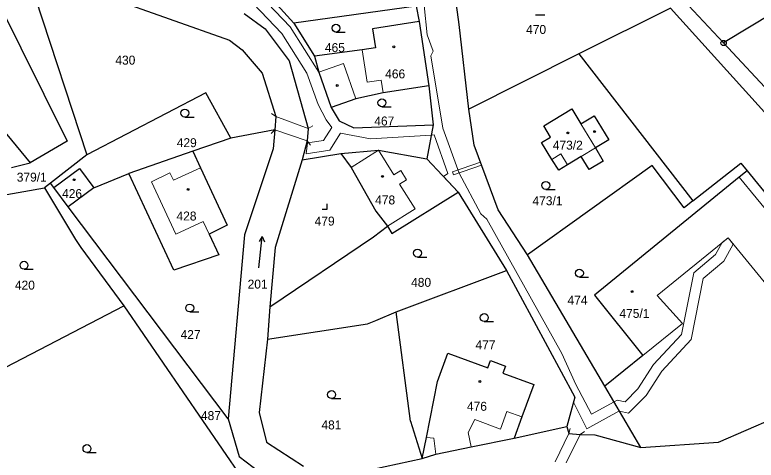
# Model space of a CAD drawing. Extents: x -727701 to -724405, y -960481 to -957284.
# Drawn here: x -726812.2 to -726671.5, y -958402.3 to -958317.7 of the extents above; entities that cross this region are included whole.
import ezdxf
from ezdxf.enums import TextEntityAlignment as Align

# ---------------------------------------------------------------- set-up
doc = ezdxf.new("R2010")
doc.units = 0
doc.header["$LTSCALE"] = 0.68
for name, color, linetype, lineweight in [('1', 7, 'Continuous', 25), ('13', 7, 'Continuous', 13), ('3', 7, 'Continuous', 25), ('4', 7, 'Continuous', 13), ('5', 7, 'Continuous', 25), ('8', 7, 'Continuous', 25)]:
    doc.layers.add(name, color=color, linetype=linetype, lineweight=lineweight)
doc.layers.add('2', color=7, linetype='Continuous')

msp = doc.modelspace()

# ---------------------------------------------------------------- linework, layer by layer
at = {"layer": '1'}
for p, q in [((-726618.94, -958287.19), (-726677.69, -958323.03)), ((-726772.79, -958304.36), (-726759.23, -958319.25)), ((-726810.21, -958308.73), (-726771.46, -958322.52)), ((-726810.21, -958308.73), (-726798.51, -958344.29)), ((-726727.9, -958319.49), (-726729.36, -958308.42)), ((-726818.24, -958309.55), (-726802.3, -958341.7)), ((-726736.03, -958316.02), (-726759.23, -958319.25)), ((-726736.03, -958316.02), (-726735.5, -958318.98)), ((-726687.74, -958316.39), (-726705.14, -958325.12)), ((-726687.74, -958316.39), (-726665.6, -958341)), ((-726684.33, -958315.89), (-726677.69, -958323.03)), ((-726768.67, -958317.43), (-726764.7, -958320.37)), ((-726759.23, -958319.25), (-726755.31, -958325.53)), ((-726735.5, -958318.98), (-726744.32, -958320.32)), ((-726735.5, -958318.98), (-726733.65, -958331.2)), ((-726764.7, -958320.37), (-726760.13, -958326.43)), ((-726744.32, -958320.32), (-726743.76, -958323.97)), ((-726726.02, -958335.6), (-726727.9, -958319.49)), ((-726771.46, -958322.52), (-726769.08, -958324.31)), ((-726677.69, -958323.03), (-726664, -958337.75)), ((-726769.08, -958324.31), (-726765.28, -958328.77)), ((-726746.29, -958324.36), (-726755.31, -958325.53)), ((-726743.76, -958323.97), (-726746.29, -958324.36)), ((-726755.31, -958325.53), (-726754.54, -958328.58)), ((-726705.14, -958325.12), (-726726.02, -958335.6)), ((-726705.14, -958325.12), (-726683.51, -958353.02)), ((-726760.13, -958326.43), (-726756.52, -958339.29)), ((-726765.28, -958328.77), (-726762.66, -958336.97)), ((-726754.54, -958328.58), (-726752.19, -958335.27)), ((-726733.65, -958331.2), (-726742.33, -958332.52)), ((-726733.65, -958331.2), (-726732.83, -958338.56)), ((-726819.9, -958332.9), (-726809.31, -958345.8)), ((-726775.94, -958332.49), (-726798.51, -958344.29)), ((-726771.24, -958341.08), (-726775.94, -958332.49)), ((-726742.33, -958332.52), (-726747.47, -958333.61)), ((-726747.47, -958333.61), (-726752.19, -958335.27)), ((-726752.19, -958335.27), (-726750.65, -958337.84)), ((-726725.06, -958342.42), (-726726.02, -958335.6)), ((-726711.82, -958338.77), (-726706.51, -958335.56)), ((-726706.51, -958335.56), (-726704.78, -958338.4)), ((-726762.66, -958336.97), (-726762.86, -958339.53)), ((-726750.65, -958337.84), (-726747.86, -958339.12)), ((-726747.86, -958339.12), (-726732.83, -958338.56)), ((-726732.83, -958338.56), (-726734, -958345.05)), ((-726710.53, -958340.89), (-726711.82, -958338.77)), ((-726762.86, -958339.53), (-726771.24, -958341.08)), ((-726762.86, -958339.53), (-726763.16, -958343.11)), ((-726756.52, -958339.29), (-726756.71, -958341.61)), ((-726802.3, -958341.7), (-726809.31, -958345.8)), ((-726771.24, -958341.08), (-726778.41, -958343.59)), ((-726756.71, -958341.61), (-726757.7, -958345.2)), ((-726712.26, -958341.96), (-726710.53, -958340.89)), ((-726699.47, -958341.43), (-726702, -958342.97)), ((-726763.16, -958343.11), (-726768.64, -958359.47)), ((-726720.45, -958354.72), (-726725.06, -958342.42)), ((-726710.32, -958345.14), (-726712.26, -958341.96)), ((-726702, -958342.97), (-726700.56, -958345.49)), ((-726798.51, -958344.29), (-726805.45, -958349.64)), ((-726778.41, -958343.59), (-726790.55, -958347.84)), ((-726778.41, -958343.59), (-726776.96, -958346.73)), ((-726757.7, -958345.2), (-726750.35, -958344)), ((-726750.35, -958344), (-726743.18, -958343.39)), ((-726750.35, -958344), (-726748.4, -958346.65)), ((-726743.18, -958343.39), (-726734, -958345.05)), ((-726704.71, -958344.62), (-726707.3, -958346.19)), ((-726703.2, -958347.09), (-726704.71, -958344.62)), ((-726812.83, -958346.68), (-726809.31, -958345.8)), ((-726757.7, -958345.2), (-726762.82, -958361.87)), ((-726734, -958345.05), (-726728.06, -958351.35)), ((-726708.97, -958347.17), (-726710.32, -958345.14)), ((-726700.56, -958345.49), (-726703.2, -958347.09)), ((-726683.51, -958353.02), (-726674.43, -958345.88)), ((-726674.43, -958345.88), (-726673.24, -958347.31)), ((-726804.82, -958350.47), (-726799.9, -958346.86)), ((-726799.9, -958346.86), (-726797.21, -958350.55)), ((-726776.96, -958346.73), (-726771.91, -958357.66)), ((-726748.4, -958346.65), (-726743.69, -958354.99)), ((-726707.3, -958346.19), (-726708.97, -958347.17)), ((-726673.24, -958347.31), (-726674.73, -958348.52)), ((-726673.24, -958347.31), (-726646.16, -958380.52)), ((-726797.21, -958350.55), (-726790.55, -958347.84)), ((-726782.03, -958366.2), (-726790.55, -958347.84)), ((-726674.73, -958348.52), (-726702.18, -958370.9)), ((-726805.45, -958349.64), (-726806.58, -958350.51)), ((-726804.82, -958350.47), (-726805.45, -958349.64)), ((-726830.51, -958354.75), (-726806.58, -958350.51)), ((-726806.58, -958350.51), (-726800.69, -958360.38)), ((-726802.1, -958354.14), (-726804.82, -958350.47)), ((-726797.21, -958350.55), (-726802.1, -958354.14)), ((-726740.66, -958359.19), (-726728.06, -958351.35)), ((-726728.06, -958351.35), (-726718.91, -958366.22)), ((-726771.73, -958394.42), (-726802.1, -958354.14)), ((-726743.69, -958354.99), (-726741.45, -958357.8)), ((-726771.91, -958357.66), (-726775.33, -958359.34)), ((-726744.13, -958359.87), (-726741.45, -958357.8)), ((-726741.45, -958357.8), (-726740.66, -958359.19)), ((-726775.33, -958359.34), (-726773.5, -958363.29)), ((-726768.64, -958359.47), (-726771.73, -958394.42)), ((-726763.84, -958373.14), (-726744.13, -958359.87)), ((-726800.69, -958360.38), (-726799.66, -958361.88)), ((-726799.66, -958361.88), (-726791.52, -958372.96)), ((-726762.82, -958361.87), (-726763.84, -958373.14)), ((-726773.5, -958363.29), (-726782.03, -958366.2)), ((-726700.25, -958388.21), (-726714.91, -958363.29)), ((-726739.83, -958374.1), (-726718.91, -958366.22)), ((-726718.91, -958366.22), (-726705.95, -958390.31)), ((-726702.18, -958370.9), (-726693.03, -958382.39)), ((-726835.12, -958395.65), (-726791.52, -958372.96)), ((-726791.52, -958372.96), (-726766.75, -958409.03)), ((-726763.84, -958373.14), (-726764.28, -958379.3)), ((-726743.71, -958375.73), (-726739.83, -958374.1)), ((-726737.11, -958394.87), (-726739.83, -958374.1)), ((-726764.28, -958379.3), (-726745.29, -958376.39)), ((-726745.29, -958376.39), (-726743.71, -958375.73)), ((-726764.28, -958379.3), (-726765.86, -958393.21)), ((-726731.96, -958387.31), (-726730.01, -958381.95)), ((-726730.01, -958381.95), (-726722.42, -958384.71)), ((-726693.03, -958382.39), (-726700.25, -958388.21)), ((-726722.42, -958384.71), (-726721.93, -958383.34)), ((-726721.93, -958383.34), (-726719.06, -958384.39)), ((-726719.06, -958384.39), (-726719.56, -958385.75)), ((-726719.56, -958385.75), (-726713.71, -958387.87)), ((-726734.1, -958397.95), (-726731.96, -958387.31)), ((-726713.71, -958387.87), (-726715.96, -958394.06)), ((-726693.41, -958399.84), (-726700.25, -958388.21)), ((-726705.95, -958390.31), (-726707.46, -958395.89)), ((-726678.65, -958398.83), (-726661.65, -958391.45)), ((-726765.86, -958393.21), (-726764.41, -958398.83)), ((-726771.73, -958394.42), (-726769.65, -958401.57)), ((-726737.11, -958394.87), (-726734.9, -958401.93)), ((-726715.96, -958394.06), (-726717.42, -958398.08)), ((-726717.42, -958398.08), (-726707.46, -958395.89)), ((-726707.46, -958395.89), (-726707.07, -958397.19)), ((-726734.9, -958401.93), (-726734.1, -958397.95)), ((-726725.6, -958399.75), (-726717.42, -958398.08)), ((-726707.07, -958397.19), (-726704.94, -958397.37)), ((-726704.94, -958397.37), (-726702.12, -958397.48)), ((-726702.12, -958397.48), (-726693.41, -958399.84)), ((-726764.41, -958398.83), (-726757.41, -958403.41)), ((-726693.41, -958399.84), (-726678.65, -958398.83)), ((-726732.3, -958401.15), (-726725.6, -958399.75)), ((-726769.65, -958401.57), (-726760.44, -958408.49)), ((-726746.61, -958404.51), (-726734.9, -958401.93)), ((-726734.9, -958401.93), (-726732.3, -958401.15))]:
    msp.add_line(p, q, dxfattribs=at)
for points in [[(-726704.78, -958338.4), (-726702.25, -958336.87), (-726699.47, -958341.43)], [(-726691.27, -958346.27), (-726714.91, -958363.29), (-726720.45, -958354.72)], [(-726683.51, -958353.02), (-726685.16, -958354.32), (-726691.27, -958346.27)]]:
    msp.add_lwpolyline(points, dxfattribs=at)
at = {"layer": '13'}
for points in [[(-726779.07, -958302.81), (-726761.52, -958321.23), (-726756.76, -958328.78), (-726754.62, -958334.72), (-726753.09, -958337.62), (-726752.07, -958339.07), (-726753.63, -958341.55), (-726756.66, -958342), (-726756.94, -958344.07), (-726752.42, -958343.4), (-726750.39, -958340.15), (-726744.7, -958341.22), (-726733.19, -958340.53), (-726732.63, -958340.5), (-726730.02, -958347.79), (-726730.85, -958348.39), (-726728.06, -958351.35), (-726718.91, -958366.22), (-726705.95, -958390.31), (-726706.21, -958391.28), (-726703.63, -958396.29), (-726697.55, -958392.97), (-726697.44, -958392.99), (-726695.72, -958393.33), (-726692.4, -958390), (-726689.43, -958385.35), (-726683.82, -958379.33), (-726681.54, -958367.75), (-726677.64, -958364.49), (-726675.86, -958361.23), (-726676.84, -958360.02), (-726677.99, -958360.95), (-726679.21, -958363.19), (-726683.37, -958366.67), (-726685.68, -958378.39), (-726691.02, -958384.12), (-726693.97, -958388.74), (-726696.38, -958391.16), (-726697.87, -958390.86), (-726698.49, -958391.2), (-726702.79, -958393.55), (-726705.72, -958387.88), (-726708.39, -958381.98), (-726722.61, -958356.49), (-726723.79, -958355.48), (-726727.9, -958347.77), (-726730.97, -958339.2), (-726733.23, -958325.48), (-726732.83, -958324.58), (-726733.92, -958321.51), (-726734.49, -958315.91)], [(-726732.83, -958338.56), (-726747.86, -958339.12), (-726750.65, -958337.84), (-726752.19, -958335.27), (-726754.54, -958328.58), (-726759.93, -958319.99), (-726774.12, -958305.1)], [(-726736.03, -958316.02), (-726735.5, -958318.98), (-726733.65, -958331.2), (-726732.83, -958338.56)]]:
    msp.add_lwpolyline(points, dxfattribs=at)
msp.add_lwpolyline([(-726729.16, -958347.52), (-726728.96, -958348.08), (-726723.64, -958346.21), (-726723.85, -958345.65)], close=True, dxfattribs=at)
at = {"layer": '3'}
for p, q in [((-726713.363, -958317.68), (-726711.613, -958317.68)), ((-726751.253, -958320.97), (-726749.503, -958320.97)), ((-726742.533, -958335.14), (-726740.783, -958335.14)), ((-726779.943, -958337.09), (-726778.193, -958337.09)), ((-726711.423, -958350.84), (-726709.673, -958350.84)), ((-726765.246, -958359.8), (-726764.85, -958360.824)), ((-726735.783, -958363.68), (-726734.033, -958363.68)), ((-726810.463, -958366), (-726808.713, -958366)), ((-726705.063, -958367.5), (-726703.313, -958367.5)), ((-726779.003, -958374.12), (-726777.253, -958374.12)), ((-726723.123, -958375.93), (-726721.373, -958375.93)), ((-726752.093, -958390.56), (-726750.343, -958390.56)), ((-726798.513, -958400.81), (-726796.763, -958400.81))]:
    msp.add_line(p, q, dxfattribs=at)
for points in [[(-726753.901, -958354.6), (-726752.9, -958354.6), (-726752.9, -958353.6)], [(-726765.873, -958365.767), (-726765.246, -958359.8), (-726765.847, -958360.72)]]:
    msp.add_lwpolyline(points, dxfattribs=at)
for centre in [(-726751.2529, -958320.2198), (-726742.5329, -958334.3898), (-726779.9429, -958336.3398), (-726711.4229, -958350.0898), (-726735.7829, -958362.9298), (-726810.4629, -958365.2498), (-726705.0629, -958366.7498), (-726779.0029, -958373.3698), (-726723.1229, -958375.1798), (-726752.0929, -958389.8098), (-726798.5129, -958400.0598)]:
    msp.add_circle(centre, 0.75, dxfattribs=at)
at = {"layer": '4'}
for p, q in [((-726745.36, -958330.48), (-726746.29, -958324.36)), ((-726754.54, -958328.58), (-726749.82, -958326.92)), ((-726749.82, -958326.92), (-726747.47, -958333.61)), ((-726742.7, -958330.08), (-726745.36, -958330.48)), ((-726742.33, -958332.52), (-726742.7, -958330.08)), ((-726763.499, -958336.425), (-726762.66, -958336.969)), ((-726762.66, -958336.97), (-726756.52, -958339.29)), ((-726755.662, -958338.775), (-726756.519, -958339.29)), ((-726702, -958342.97), (-726704.78, -958338.4)), ((-726763.568, -958340.237), (-726762.861, -958339.53)), ((-726756.71, -958341.61), (-726762.86, -958339.53)), ((-726756.108, -958342.409), (-726756.71, -958341.611)), ((-726704.71, -958344.62), (-726702, -958342.97)), ((-726748.4, -958346.65), (-726743.18, -958343.39)), ((-726743.18, -958343.39), (-726740.27, -958348.06)), ((-726710.32, -958345.14), (-726708.58, -958344.1)), ((-726708.58, -958344.1), (-726707.3, -958346.19)), ((-726782.1, -958349.09), (-726776.96, -958346.73)), ((-726740.27, -958348.06), (-726738.97, -958347.25)), ((-726738.97, -958347.25), (-726737.88, -958349.01)), ((-726786.29, -958349.4), (-726782.77, -958347.7)), ((-726782.77, -958347.7), (-726782.1, -958349.09)), ((-726674.73, -958348.52), (-726655.02, -958372.69)), ((-726781.67, -958359.36), (-726786.29, -958349.4)), ((-726737.88, -958349.01), (-726739.18, -958349.82)), ((-726739.18, -958349.82), (-726736.23, -958354.54)), ((-726736.23, -958354.54), (-726741.45, -958357.8)), ((-726776.44, -958356.94), (-726781.67, -958359.36)), ((-726775.33, -958359.34), (-726776.44, -958356.94)), ((-726676.84, -958360.02), (-726690.31, -958371)), ((-726661.93, -958378.32), (-726676.84, -958360.02)), ((-726690.31, -958371), (-726685.5, -958376.32)), ((-726685.5, -958376.32), (-726693.03, -958382.39)), ((-726718.82, -958393.02), (-726720.05, -958396.4)), ((-726715.96, -958394.06), (-726718.82, -958393.02)), ((-726724.9, -958394.55), (-726726.15, -958397)), ((-726720.05, -958396.4), (-726724.9, -958394.55)), ((-726706.794, -958396.228), (-726707.069, -958397.19)), ((-726732.7, -958398.1), (-726734.1, -958397.95)), ((-726732.3, -958401.15), (-726732.7, -958398.1)), ((-726726.15, -958397), (-726725.6, -958399.75)), ((-726709.69, -958402.61), (-726707.07, -958397.19)), ((-726704.94, -958397.37), (-726707.59, -958402.79)), ((-726704.12, -958396.797), (-726704.939, -958397.37))]:
    msp.add_line(p, q, dxfattribs=at)
at = {"layer": '5'}
for centre in [(-726740.2768, -958323.7492), (-726751.0068, -958331.0892), (-726707.2668, -958340.1192), (-726702.1668, -958339.8592), (-726800.9368, -958348.9992), (-726742.4368, -958348.3692), (-726779.3268, -958350.8392), (-726695.0668, -958370.2592), (-726723.9368, -958387.3392)]:
    msp.add_circle(centre, 0.175, dxfattribs=at)
at = {"layer": '8'}
for radius in [0.5, 0.0303]:
    msp.add_circle((-726677.69, -958323.0299), radius, dxfattribs=at)

# ---------------------------------------------------------------- texts
at = {"layer": '2'}
for s, p in [('470', (-726715.17, -958321.315)), ('465', (-726753.36, -958324.755)), ('466', (-726741.92, -958329.745)), ('467', (-726743.98, -958338.695)), ('429', (-726781.47, -958342.815)), ('426', (-726803.24, -958352.485)), ('478', (-726743.82, -958353.695)), ('428', (-726781.52, -958356.745)), ('479', (-726755.3, -958357.705)), ('420', (-726812.19, -958369.875)), ('201', (-726768.02, -958369.675)), ('480', (-726737, -958369.345)), ('474', (-726707.31, -958372.715)), ('475/1', (-726697.46, -958375.245)), ('427', (-726780.75, -958379.265)), ('477', (-726724.77, -958381.205)), ('476', (-726726.4, -958392.885)), ('487', (-726776.88, -958394.655)), ('481', (-726754.02, -958396.425))]:
    msp.add_text(s, height=1.7, dxfattribs=at).set_placement(p)
for s, p in [('430', (-726791.229, -958327.135)), ('473/2', (-726707.26, -958343.285)), ('379/1', (-726808.99, -958349.365)), ('473/1', (-726711.12, -958353.845))]:
    msp.add_text(s, height=1.7, dxfattribs=at).set_placement(p, align=Align.CENTER)

doc.saveas('drawing.dxf')
